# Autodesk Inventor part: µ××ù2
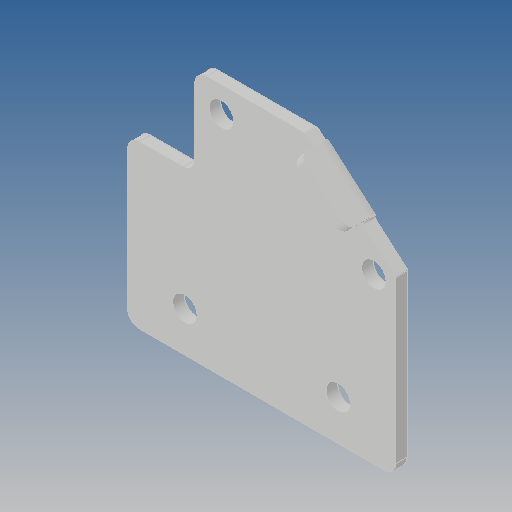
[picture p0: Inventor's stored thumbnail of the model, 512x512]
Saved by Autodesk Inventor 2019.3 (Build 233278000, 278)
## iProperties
Created: 2017-08
Part Number: µ××ù2
Material: Ogólny
Document SubType Name: Modeling
Designer: Admin
Density: 1 g/cm^3
Appearance: Domyślna
Author: Admin
Revision Number: ÈÎºÎ
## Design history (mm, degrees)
feature "ÊäÈë1"
node "Bryła1"
